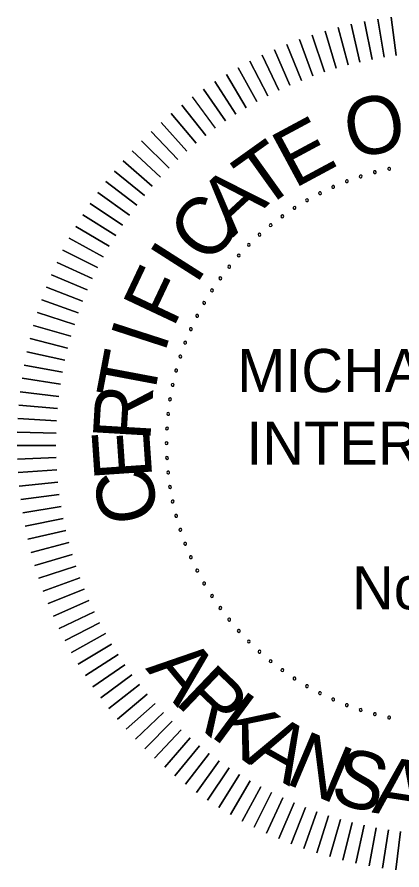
# Model space of a CAD drawing. Extents: x 152 to 3426, y 67 to 2142.
# Drawn here: x 2711.4 to 2822.6, y 308.7 to 555.6 of the extents above; entities that cross this region are included whole.
import ezdxf

# ---------------------------------------------------------------- set-up
doc = ezdxf.new("R2010")
doc.units = 0
doc.layers.add('G-ANNO-TEXT', color=7, linetype='Continuous')

msp = doc.modelspace()

# ---------------------------------------------------------------- linework, layer by layer
at = {"layer": 'G-ANNO-TEXT'}
for points in [[(2821.02, 544.49), (2819.55, 555.62)], [(2819.55, 555.62), (2821.02, 544.49)], [(2810.52, 542.6), (2808.01, 553.54)], [(2808.01, 553.54), (2810.52, 542.6)], [(2814, 543.34), (2811.83, 554.35)], [(2811.83, 554.35), (2814, 543.34)], [(2817.5, 543.97), (2815.68, 555.04)], [(2815.68, 555.04), (2817.5, 543.97)], [(2803.64, 540.79), (2800.45, 551.55)], [(2800.45, 551.55), (2803.64, 540.79)], [(2807.06, 541.75), (2804.21, 552.6)], [(2804.21, 552.6), (2807.06, 541.75)], [(2796.89, 538.56), (2793.03, 549.09)], [(2793.03, 549.09), (2796.89, 538.56)], [(2800.24, 539.73), (2796.72, 550.38)], [(2796.72, 550.38), (2800.24, 539.73)], [(2790.29, 535.9), (2785.77, 546.17)], [(2785.77, 546.17), (2790.29, 535.9)], [(2793.57, 537.28), (2789.38, 547.69)], [(2789.38, 547.69), (2793.57, 537.28)], [(2787.05, 534.42), (2782.22, 544.55)], [(2782.22, 544.55), (2787.05, 534.42)], [(2780.74, 531.15), (2775.27, 540.96)], [(2775.27, 540.96), (2780.74, 531.15)], [(2783.87, 532.84), (2778.72, 542.81)], [(2778.72, 542.81), (2783.87, 532.84)], [(2777.66, 529.37), (2771.89, 539)], [(2771.89, 539), (2777.66, 529.37)], [(2774.63, 527.5), (2768.57, 536.94)], [(2768.57, 536.94), (2774.63, 527.5)], [(2771.67, 525.53), (2765.31, 534.78)], [(2765.31, 534.78), (2771.67, 525.53)], [(2768.77, 523.47), (2762.13, 532.51)], [(2765.94, 521.32), (2759.01, 530.15)], [(2759.01, 530.15), (2765.94, 521.32)], [(2763.18, 519.08), (2755.98, 527.69)], [(2755.98, 527.69), (2763.18, 519.08)], [(2760.49, 516.75), (2753.02, 525.13)], [(2753.02, 525.13), (2760.49, 516.75)], [(2757.87, 514.34), (2750.14, 522.48)], [(2750.14, 522.48), (2757.87, 514.34)], [(2755.33, 511.86), (2747.35, 519.75)], [(2747.35, 519.75), (2755.33, 511.86)], [(2752.87, 509.29), (2744.64, 516.92)], [(2744.64, 516.92), (2752.87, 509.29)], [(2750.49, 506.64), (2742.03, 514.02)], [(2742.03, 514.02), (2750.49, 506.64)], [(2748.19, 503.93), (2739.51, 511.03)], [(2739.51, 511.03), (2748.19, 503.93)], [(2745.99, 501.14), (2737.08, 507.97)], [(2737.08, 507.97), (2745.99, 501.14)], [(2743.87, 498.28), (2734.75, 504.83)], [(2734.75, 504.83), (2743.87, 498.28)], [(2741.84, 495.36), (2732.52, 501.62)], [(2732.52, 501.62), (2741.84, 495.36)], [(2739.9, 492.38), (2730.39, 498.34)], [(2730.39, 498.34), (2739.9, 492.38)], [(2738.06, 489.33), (2728.37, 494.99)], [(2728.37, 494.99), (2738.06, 489.33)], [(2736.31, 486.23), (2726.45, 491.59)], [(2726.45, 491.59), (2736.31, 486.23)], [(2734.67, 483.08), (2724.64, 488.12)], [(2724.64, 488.12), (2734.67, 483.08)], [(2733.12, 479.88), (2722.94, 484.6)], [(2722.94, 484.6), (2733.12, 479.88)], [(2731.67, 476.63), (2721.35, 481.03)], [(2721.35, 481.03), (2731.67, 476.63)], [(2730.33, 473.34), (2719.87, 477.41)], [(2719.87, 477.41), (2730.33, 473.34)], [(2729.09, 470), (2718.51, 473.74)], [(2718.51, 473.74), (2729.09, 470)], [(2727.96, 466.63), (2717.27, 470.04)], [(2717.27, 470.04), (2727.96, 466.63)], [(2726.93, 463.23), (2716.14, 466.3)], [(2716.14, 466.3), (2726.93, 463.23)], [(2726.01, 459.79), (2715.13, 462.52)], [(2715.13, 462.52), (2726.01, 459.79)], [(2725.2, 456.33), (2714.24, 458.71)], [(2714.24, 458.71), (2725.2, 456.33)], [(2724.5, 452.84), (2713.47, 454.88)], [(2713.47, 454.88), (2724.5, 452.84)], [(2723.91, 449.33), (2712.82, 451.03)], [(2712.82, 451.03), (2723.91, 449.33)], [(2723.43, 445.81), (2712.29, 447.15)], [(2712.29, 447.15), (2723.43, 445.81)], [(2723.06, 442.27), (2711.88, 443.27)], [(2711.88, 443.27), (2723.06, 442.27)], [(2722.8, 438.72), (2711.59, 439.37)], [(2711.59, 439.37), (2722.8, 438.72)], [(2722.65, 435.17), (2711.43, 435.46)], [(2711.43, 435.46), (2722.65, 435.17)], [(2722.61, 431.61), (2711.39, 431.55)], [(2711.39, 431.55), (2722.61, 431.61)], [(2722.69, 428.06), (2711.47, 427.64)], [(2711.47, 427.64), (2722.69, 428.06)], [(2722.88, 424.51), (2711.68, 423.74)], [(2711.68, 423.74), (2722.88, 424.51)], [(2723.18, 420.96), (2712.01, 419.84)], [(2712.01, 419.84), (2723.18, 420.96)], [(2723.59, 417.43), (2712.46, 415.96)], [(2712.46, 415.96), (2723.59, 417.43)], [(2724.11, 413.91), (2713.03, 412.09)], [(2713.03, 412.09), (2724.11, 413.91)], [(2724.74, 410.41), (2713.73, 408.25)], [(2713.73, 408.25), (2724.74, 410.41)], [(2725.48, 406.93), (2714.54, 404.42)], [(2714.54, 404.42), (2725.48, 406.93)], [(2726.33, 403.48), (2715.47, 400.63)], [(2715.47, 400.63), (2726.33, 403.48)], [(2727.29, 400.05), (2716.53, 396.86)], [(2716.53, 396.86), (2727.29, 400.05)], [(2728.35, 396.66), (2717.7, 393.13)], [(2717.7, 393.13), (2728.35, 396.66)], [(2729.52, 393.3), (2718.98, 389.44)], [(2718.98, 389.44), (2729.52, 393.3)], [(2730.8, 389.98), (2720.39, 385.79)], [(2720.39, 385.79), (2730.8, 389.98)], [(2732.18, 386.7), (2721.9, 382.19)], [(2721.9, 382.19), (2732.18, 386.7)], [(2733.66, 383.47), (2723.53, 378.63)], [(2723.53, 378.63), (2733.66, 383.47)], [(2735.24, 380.28), (2725.27, 375.13)], [(2725.27, 375.13), (2735.24, 380.28)], [(2736.92, 377.15), (2727.12, 371.69)], [(2727.12, 371.69), (2736.92, 377.15)], [(2738.7, 374.07), (2729.07, 368.3)], [(2729.07, 368.3), (2738.7, 374.07)], [(2740.58, 371.05), (2731.13, 364.98)], [(2731.13, 364.98), (2740.58, 371.05)], [(2742.55, 368.09), (2733.3, 361.73)], [(2733.3, 361.73), (2742.55, 368.09)], [(2744.61, 365.19), (2735.57, 358.54)], [(2735.57, 358.54), (2744.61, 365.19)], [(2746.76, 362.36), (2737.93, 355.43)], [(2737.93, 355.43), (2746.76, 362.36)], [(2749, 359.59), (2740.39, 352.39)], [(2740.39, 352.39), (2749, 359.59)], [(2751.32, 356.9), (2742.95, 349.43)], [(2742.95, 349.43), (2751.32, 356.9)], [(2753.73, 354.28), (2745.59, 346.56)], [(2745.59, 346.56), (2753.73, 354.28)], [(2756.22, 351.74), (2748.33, 343.76)], [(2748.33, 343.76), (2756.22, 351.74)], [(2758.79, 349.28), (2751.15, 341.06)], [(2751.15, 341.06), (2758.79, 349.28)], [(2754.06, 338.44), (2761.43, 346.9)], [(2761.43, 346.9), (2754.06, 338.44)], [(2757.04, 335.92), (2764.15, 344.61)], [(2764.15, 344.61), (2757.04, 335.92)], [(2760.11, 333.49), (2766.94, 342.4)], [(2766.94, 342.4), (2760.11, 333.49)], [(2763.25, 331.16), (2769.79, 340.28)], [(2769.79, 340.28), (2763.25, 331.16)], [(2766.46, 328.93), (2772.72, 338.25)], [(2772.72, 338.25), (2766.46, 328.93)], [(2769.74, 326.81), (2775.7, 336.31)], [(2775.7, 336.31), (2769.74, 326.81)], [(2773.08, 324.78), (2778.74, 334.47)], [(2778.74, 334.47), (2773.08, 324.78)], [(2776.49, 322.86), (2781.84, 332.73)], [(2781.84, 332.73), (2776.49, 322.86)], [(2779.95, 321.05), (2784.99, 331.08)], [(2784.99, 331.08), (2779.95, 321.05)], [(2783.47, 319.35), (2788.2, 329.53)], [(2788.2, 329.53), (2783.47, 319.35)], [(2787.05, 317.76), (2791.45, 328.09)], [(2791.45, 328.09), (2787.05, 317.76)], [(2790.67, 316.29), (2794.74, 326.75)], [(2794.74, 326.75), (2790.67, 316.29)], [(2794.33, 314.93), (2798.07, 325.51)], [(2798.07, 325.51), (2794.33, 314.93)], [(2798.04, 313.68), (2801.45, 324.37)], [(2801.45, 324.37), (2798.04, 313.68)], [(2801.78, 312.55), (2804.85, 323.35)], [(2804.85, 323.35), (2801.78, 312.55)], [(2805.56, 311.54), (2808.29, 322.43)], [(2808.29, 322.43), (2805.56, 311.54)], [(2809.36, 310.65), (2811.75, 321.62)], [(2811.75, 321.62), (2809.36, 310.65)], [(2813.19, 309.88), (2815.24, 320.92)], [(2815.24, 320.92), (2813.19, 309.88)], [(2817.05, 309.23), (2818.74, 320.32)], [(2818.74, 320.32), (2817.05, 309.23)], [(2820.92, 308.7), (2822.27, 319.84)], [(2822.27, 319.84), (2820.92, 308.7)]]:
    msp.add_lwpolyline(points, dxfattribs=at)
for centre, start, end in [((2818.95, 511.69), 12, 192), ((2818.95, 511.69), 192, 12), ((2810.73, 509.48), 18, 198), ((2810.73, 509.48), 198, 18), ((2814.81, 510.69), 15, 195), ((2814.81, 510.69), 195, 15), ((2802.8, 506.44), 24, 204), ((2802.8, 506.44), 204, 24), ((2806.73, 508.07), 21, 201), ((2806.73, 508.07), 201, 21), ((2798.96, 504.61), 27, 207), ((2798.96, 504.61), 207, 27), ((2795.22, 502.58), 30, 210), ((2795.22, 502.58), 210, 30), ((2791.6, 500.36), 33, 213), ((2791.6, 500.36), 213, 33), ((2788.09, 497.95), 36, 216), ((2788.09, 497.95), 216, 36), ((2784.72, 495.36), 39, 219), ((2784.72, 495.36), 219, 39), ((2781.49, 492.6), 42, 222), ((2781.49, 492.6), 222, 42), ((2778.4, 489.67), 45, 225), ((2778.4, 489.67), 225, 45), ((2775.48, 486.59), 48, 228), ((2775.48, 486.59), 228, 48), ((2772.72, 483.36), 51, 231), ((2772.72, 483.36), 231, 51), ((2770.13, 479.98), 54, 234), ((2770.13, 479.98), 234, 54), ((2767.72, 476.48), 57, 237), ((2767.72, 476.48), 237, 57), ((2765.5, 472.85), 60, 240), ((2765.5, 472.85), 240, 60), ((2763.47, 469.12), 63, 243), ((2763.47, 469.12), 243, 63), ((2761.64, 465.28), 66, 246), ((2761.64, 465.28), 246, 66), ((2760.01, 461.35), 69, 249), ((2760.01, 461.35), 249, 69), ((2758.59, 457.34), 72, 252), ((2758.59, 457.34), 252, 72), ((2757.38, 453.27), 75, 255), ((2757.38, 453.27), 255, 75), ((2756.39, 449.13), 78, 258), ((2756.39, 449.13), 258, 78), ((2755.62, 444.95), 81, 261), ((2755.62, 444.95), 261, 81), ((2755.06, 440.73), 84, 264), ((2755.06, 440.73), 264, 84), ((2754.73, 436.5), 87, 267), ((2754.73, 436.5), 267, 87), ((2754.62, 432.25), 90, 270), ((2754.62, 432.25), 270, 90), ((2754.73, 427.99), 93, 273), ((2754.73, 427.99), 273, 93), ((2755.06, 423.76), 96, 276), ((2755.06, 423.76), 276, 96), ((2755.62, 419.54), 99, 279), ((2755.62, 419.54), 279, 99), ((2756.39, 415.36), 102, 282), ((2756.39, 415.36), 282, 102), ((2757.38, 411.23), 105, 285), ((2757.38, 411.23), 285, 105), ((2758.59, 407.15), 108, 288), ((2758.59, 407.15), 288, 108), ((2760.01, 403.14), 111, 291), ((2760.01, 403.14), 291, 111), ((2761.64, 399.21), 114, 294), ((2761.64, 399.21), 294, 114), ((2763.47, 395.37), 117, 297), ((2763.47, 395.37), 297, 117), ((2765.5, 391.64), 120, 300), ((2765.5, 391.64), 300, 120), ((2767.72, 388.01), 123, 303), ((2767.72, 388.01), 303, 123), ((2770.13, 384.51), 126, 306), ((2770.13, 384.51), 306, 126), ((2772.72, 381.14), 129, 309), ((2772.72, 381.14), 309, 129), ((2775.48, 377.9), 132, 312), ((2775.48, 377.9), 312, 132), ((2778.4, 374.82), 135, 315), ((2778.4, 374.82), 315, 135), ((2781.49, 371.89), 138, 318), ((2781.49, 371.89), 318, 138), ((2784.72, 369.13), 141, 321), ((2784.72, 369.13), 321, 141), ((2788.09, 366.54), 144, 324), ((2788.09, 366.54), 324, 144), ((2791.6, 364.13), 147, 327), ((2791.6, 364.13), 327, 147), ((2795.22, 361.91), 150, 330), ((2795.22, 361.91), 330, 150), ((2798.96, 359.88), 153, 333), ((2798.96, 359.88), 333, 153), ((2802.8, 358.05), 156, 336), ((2802.8, 358.05), 336, 156), ((2806.73, 356.42), 159, 339), ((2806.73, 356.42), 339, 159), ((2810.73, 355.01), 162, 342), ((2810.73, 355.01), 342, 162), ((2814.81, 353.8), 165, 345), ((2814.81, 353.8), 345, 165), ((2818.95, 352.81), 348, 168), ((2818.95, 352.81), 168, 348)]:
    msp.add_arc(centre, 0.417, start, end, dxfattribs=at)

# ---------------------------------------------------------------- texts
for s, rotation, p in [('O', 10.7295, (2807.67, 514.57)), ('E', 28.279, (2791.49, 505.84)), ('T', 35.5725, (2782.18, 499.39)), ('A', 42.8659, (2773.72, 491.68)), ('C', 50.1594, (2766.71, 483.35)), ('I', 57.4529, (2763.09, 477.78)), ('F', 64.7464, (2756.54, 465.32)), ('I', 72.0398, (2753.96, 457.99)), ('T', 79.3333, (2750.65, 443.63)), ('R', 86.6268, (2749.88, 432.61)), ('E', 93.9203, (2750.5, 422.2)), ('C', 101.2137, (2752.63, 410.61)), ('A', 309.5859, (2748.37, 366.98)), ('R', 316.3356, (2756.64, 357.15)), ('K', 323.6428, (2766.84, 347.69)), ('A', 330.3925, (2777.25, 340.17)), ('N', 337.1422, (2788.48, 333.92)), ('S', 344.4494, (2801.37, 328.7)), ('A', 351.1991, (2813.78, 325.36))]:
    msp.add_text(s, height=16.67, rotation=rotation, dxfattribs=at).set_placement(p)
for s, height, p in [('MICHAEL BAKER', 12.5016, (2775, 447.02)), (' INTERNATIONAL', 12.5016, (2772.99, 426)), (' No. 1126', 12.502, (2803.57, 384.14))]:
    msp.add_text(s, height=height, dxfattribs=at).set_placement(p)

doc.saveas('drawing.dxf')
